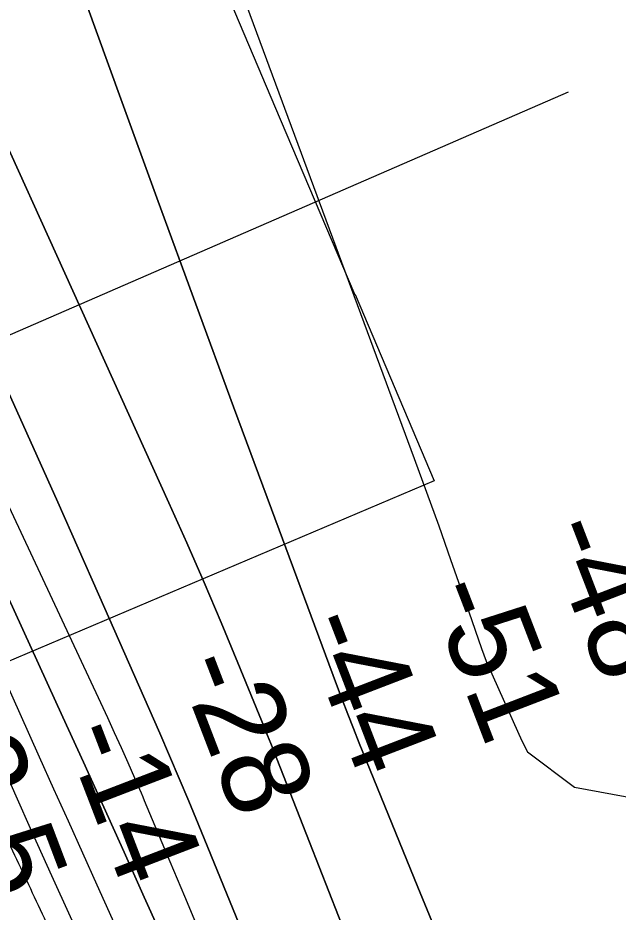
# Model space of a CAD drawing. Extents: x 3684037 to 3722149, y 433263 to 459021.
# Drawn here: x 3706787 to 3707248, y 445146 to 445833 of the extents above; entities that cross this region are included whole.
import ezdxf

# ---------------------------------------------------------------- set-up
doc = ezdxf.new("R2010")
doc.units = 0
for name, color, linetype in [('V-RIVR-EDGE', 7, 'Continuous'), ('V-RIVR-RANG', 7, 'Continuous'), ('V-RRAP-RVMT', 7, 'Continuous'), ('V-TOPO-DPTH', 7, 'Continuous'), ('V-TOPO-MAJR', 7, 'Continuous'), ('V-TOPO-MINR', 7, 'Continuous'), ('V-TOPO-WATR', 7, 'Continuous')]:
    doc.layers.add(name, color=color, linetype=linetype)

msp = doc.modelspace()

# ---------------------------------------------------------------- linework, layer by layer
at = {"layer": 'V-RIVR-EDGE'}
for points in [[(3707057.63, 450460), (3707081.52, 450431), (3707105.39, 450392.51), (3707125.2, 450359), (3707163.49, 450300.12), (3707183.76, 450270.23), (3707206.7, 450223.15), (3707227.4, 450181.5), (3707252.17, 450142.1), (3707265.67, 450117.2), (3707275.12, 450098.64), (3707318.38, 450037.94), (3707353.07, 449985.41), (3707385.06, 449939.66), (3707406.23, 449908.41), (3707430.1, 449871.27), (3707455.78, 449833.68), (3707495.45, 449785.2), (3707517.08, 449753.49), (3707534.2, 449727.23), (3707562.13, 449687.82), (3707582.83, 449647.07), (3707592.72, 449623.99), (3707603.99, 449607.68), (3707632.37, 449565.11), (3707692.27, 449470.46), (3707727.83, 449403.91), (3707751.67, 449355.47), (3707768.33, 449325.13), (3707817.4, 449240), (3707854.79, 449182.03), (3707880.91, 449141.73), (3707898.94, 449116.36), (3707960.23, 449034.82), (3707990.86, 448990.44), (3708021.04, 448942.43), (3708046.24, 448893.54), (3708087.2, 448819.73), (3708107.48, 448788.94), (3708130.45, 448754.06), (3708144.4, 448727.8), (3708155.18, 448700.19), (3708176.37, 448674.82), (3708204.31, 448634.06), (3708224.57, 448599.19), (3708242.58, 448567.5), (3708259.67, 448533.09), (3708300.54, 448421.76), (3708313.13, 448390.98), (3708333.36, 448345.26), (3708350.46, 448310.4), (3708400.43, 448222.56), (3708436, 448162.79), (3708462.58, 448121.12), (3708493.64, 448064.07), (3708520.62, 448004.32), (3708547.17, 447952.26), (3708560.65, 447921.03), (3708599.29, 447820.1), (3708618.62, 447774.38), (3708636.6, 447732.29), (3708686.04, 447611.44), (3708708.97, 447557.58), (3708728.76, 447517.74), (3708790.87, 447400.93), (3708813.79, 447342.99), (3708823.69, 447322.62), (3708832.7, 447310.39), (3708843.99, 447304.94), (3708854.83, 447299.94), (3708866.57, 447292.22), (3708878.28, 447274.56), (3708903.02, 447223.86), (3708928.62, 447154.16), (3708946.56, 447092.62), (3708972.63, 447032.42), (3709004.55, 446957.28), (3709022.09, 446919.26), (3709036.9, 446872.65), (3709065.65, 446798.42), (3709084.55, 446762.2), (3709116.06, 446705.15), (3709133.17, 446676.17), (3709190.81, 446579.27), (3709228.65, 446520.4), (3709242.18, 446506.8), (3709273.72, 446461.5), (3709296.22, 446418.04), (3709323.65, 446357.84), (3709346.13, 446307.14), (3709405.05, 446179.94), (3709417.62, 446143.28), (3709426.98, 446089), (3709431.45, 446069.09), (3709442.24, 446043.29), (3709459.81, 446017.93), (3709485.03, 445975.81), (3709516.54, 445917.41), (3709528.22, 445886.18), (3709547.07, 445830.07), (3709579.84, 445736.39), (3709592.41, 445699.28), (3709614.43, 445642.25), (3709638.73, 445596.07), (3709660.32, 445552.16), (3709689.1, 445487.43), (3709716.1, 445435.36), (3709727.8, 445413.18), (3709766.95, 445336.67), (3709796.19, 445272.84), (3709817.77, 445223.5), (3709885.21, 445070.05), (3709914.01, 445011.65), (3709955.32, 444895.8), (3709967.01, 444870), (3709990.89, 444833.77), (3710021.5, 444778.98), (3710062.05, 444721.45), (3710099, 444671.17), (3710125.54, 444614.59), (3710149.37, 444558.91), (3710206.48, 444434.88), (3710232.57, 444377.84), (3710255.95, 444325.79), (3710301.83, 444226.65), (3710336.44, 444144.73), (3710353.07, 444103.09), (3710397.08, 443983.15), (3710422.25, 443922.96), (3710475.81, 443823.35), (3710506.44, 443776.25), (3710521.29, 443745.01), (3710531.13, 443701.58), (3710571.1, 443591.61), (3710592.23, 443543.17), (3710610.23, 443506.96), (3710643.1, 443453.52), (3710685.41, 443374.74), (3710721.42, 443310.44), (3710726.82, 443298.22), (3710725.87, 443280.14), (3710724.91, 443258.89), (3710728.49, 443241.7), (3710736.59, 443228.11), (3710746.51, 443216.79), (3710761.87, 443209.97), (3710784.47, 443208.1), (3710799.86, 443212.58), (3710819.78, 443223.39), (3710828.83, 443224.27), (3710831.98, 443222), (3710845.47, 443189.86), (3710847.7, 443178.55), (3710844.52, 443169.52), (3710837.71, 443158.23), (3710824.1, 443142.44), (3710796, 443115.83), (3710790.11, 443110.87), (3710787.84, 443107.71), (3710786.47, 443099.58), (3710789.13, 443080.58), (3710800.82, 443053.87), (3710807.11, 443036.22), (3710810.72, 443032.6), (3710815.22, 443023.09), (3710815.19, 443014.5), (3710814.27, 443006.82), (3710817.86, 442996.41), (3710822.81, 442987.35), (3710832.3, 442981.9), (3710839.97, 442976.46), (3710855.3, 442958.33), (3710863.4, 442945.65), (3710869.69, 442927.55), (3710881.85, 442907.17)], [(3705459.26, 448025.43), (3705478.18, 447991.02), (3705490.65, 447962.68), (3705497.89, 447946.89), (3705515.2, 447915.31), (3705550.22, 447853.76), (3705577.2, 447806.38), (3705592.09, 447777.23), (3705613.01, 447735.52), (3705627.09, 447702.74), (3705648.41, 447660.63), (3705670.94, 447613.26), (3705688.64, 447575.61), (3705703.12, 447542.82), (3705728.05, 447487.77), (3705750.16, 447433.12), (3705764.23, 447399.52), (3705787.56, 447350.54), (3705800.43, 447321.8), (3705823.77, 447277.66), (3705853.13, 447212.89), (3705867.2, 447179.7), (3705884.51, 447148.52), (3705906.22, 447095.49), (3705936, 447039.61), (3705952.47, 446996.31), (3705954.47, 446986.6), (3705964.51, 446959.07), (3705978.19, 446928.31), (3706001.93, 446883.77), (3706017.22, 446850.17), (3706031.3, 446824.25), (3706060.3, 446774.85), (3706084.87, 446736.78), (3706095.75, 446723.41), (3706096.15, 446720.17), (3706091.28, 446714.52), (3706089.66, 446713.31), (3706090.46, 446708.86), (3706096.11, 446705.61), (3706102.98, 446703.57), (3706108.63, 446696.69), (3706116.28, 446683.32), (3706129.96, 446657.01), (3706163.36, 446591.82), (3706169.39, 446575.63), (3706187.09, 446537.58), (3706212.81, 446473.62), (3706230.09, 446432.33), (3706247.4, 446398.32), (3706265.12, 446371.19), (3706278.81, 446345.27), (3706293.68, 446309.65), (3706314.59, 446262.29), (3706333.51, 446225.85), (3706356.04, 446180.1), (3706380.19, 446133.54), (3706396.28, 446102.36), (3706412.79, 446074.82), (3706429.69, 446038.79), (3706446.98, 445997.91), (3706455.38, 445962.3), (3706478.24, 445886.22), (3706492.71, 445852.22), (3706510.4, 445809.72), (3706528.1, 445771.66), (3706558.26, 445705.27), (3706582.81, 445657.09), (3706597.69, 445624.3), (3706628.26, 445558.31), (3706659.61, 445483.02), (3706677.69, 445432.84), (3706696.97, 445381.03), (3706750.05, 445262.42), (3706782.63, 445193.19), (3706806.77, 445141.78), (3706827.68, 445093.6), (3706850.97, 445029.25), (3706864.2, 444984.33), (3706871.8, 444949.54), (3706889.46, 444896.93), (3706899.9, 444865.77), (3706912.35, 444832.17), (3706928.85, 444798.16), (3706942.54, 444773.46), (3706966.27, 444725.28), (3706990.42, 444679.53), (3707016.98, 444624.47), (3707033.86, 444586.01), (3707080.51, 444481.98), (3707095.38, 444444.74), (3707112.27, 444405.07), (3707123.13, 444381.18), (3707171.39, 444273.5), (3707203.15, 444200.64), (3707218.02, 444163.8), (3707250.2, 444096.19), (3707257.43, 444074.34), (3707269.88, 444041.55), (3707288.36, 443990.56), (3707304.03, 443950.08), (3707342.97, 443837.97), (3707365.86, 443772.01), (3707378.69, 443728.71), (3707379.87, 443714.15), (3707381.06, 443702.82), (3707387.47, 443682.18), (3707398.33, 443657.08), (3707418.05, 443619.03), (3707438.98, 443578.54), (3707454.25, 443542.11), (3707473.14, 443492.73), (3707483.18, 443464.39), (3707531.06, 443368.04), (3707542.73, 443344.96), (3707550.76, 443323.91), (3707556.78, 443302.46), (3707556.76, 443297.61), (3707558.76, 443289.12), (3707568.43, 443273.32), (3707583.72, 443244.57), (3707593.78, 443221.9), (3707598.21, 443213.4), (3707609.51, 443204.88), (3707611.91, 443195.17), (3707611.87, 443180.61), (3707615.48, 443168.07), (3707621.91, 443150.26), (3707634.38, 443126.78), (3707648.07, 443102.08), (3707655.3, 443081.84), (3707660.54, 443073.33), (3707674.23, 443051.47), (3707678.64, 443034.07), (3707682.63, 443015.46), (3707689.47, 442998.45), (3707701.92, 442964.46), (3707713.96, 442928.44), (3707721.18, 442903.35), (3707726.4, 442888.78), (3707738.08, 442871.77), (3707743.71, 442857.2), (3707744.49, 442845.06), (3707747.27, 442826.05), (3707753.71, 442815.52), (3707762.98, 442801.35), (3707770.21, 442783.94), (3707772.59, 442762.1), (3707776.17, 442738.23), (3707779.76, 442720.03), (3707786.59, 442702.62), (3707805.5, 442663.35), (3707822.8, 442627.32), (3707832.03, 442599.39), (3707839.25, 442573.9), (3707845.68, 442561.35), (3707852.54, 442552.44), (3707860.19, 442541.9), (3707869.47, 442530.56), (3707886.39, 442507.87), (3707898.86, 442479.94), (3707916.14, 442434.61), (3707928.58, 442395.76), (3707943.44, 442356.5), (3707965.58, 442316.41), (3707989.73, 442269.04), (3708009.84, 442227.74), (3708024.72, 442192.53), (3708061.32, 442114.39), (3708074.2, 442088.48), (3708094.31, 442045.57), (3708116.02, 441996.58), (3708126.06, 441968.25), (3708137.69, 441927.79), (3708147.33, 441899.46), (3708157.76, 441868.3), (3708179.06, 441812.44), (3708203.96, 441746.87), (3708227.69, 441693.84), (3708249.81, 441646.07), (3708265.1, 441615.3), (3708271.52, 441595.87), (3708278.37, 441582.11), (3708308.11, 441508.44), (3708330.63, 441457.84), (3708349.91, 441405.22), (3708369.56, 441340.07), (3708384.01, 441295.55), (3708395.26, 441268.43), (3708411.76, 441234.83), (3708423.42, 441209.33), (3708441.12, 441169.65), (3708458.42, 441135.24), (3708469.27, 441110.55), (3708475.29, 441089.1), (3708486.95, 441061.57), (3708507.06, 441017.45), (3708523.54, 440978.59), (3708539.2, 440935.69), (3708564.14, 440883.06), (3708587.09, 440841.35), (3708595.14, 440826.77), (3708600.35, 440809.37), (3708606.75, 440778.22), (3708615.59, 440755.15), (3708636.86, 440692.01), (3708652.92, 440644.26), (3708673.41, 440592.04), (3708688.69, 440554.4), (3708705.96, 440506.64), (3708725.66, 440462.92), (3708743.35, 440422.44), (3708759.44, 440387.62), (3708800.05, 440293.31), (3708820.96, 440246.35), (3708835.03, 440211.54), (3708849.1, 440180.36), (3708876.06, 440124.9), (3708892.16, 440093.72), (3708912.28, 440054.85), (3708922.33, 440030.97), (3708931.96, 439999.81), (3708939.18, 439978.77), (3708948.02, 439954.08), (3708952.41, 439931.83), (3708956, 439911.6), (3708960.02, 439899.46), (3708969.65, 439870.32), (3708986.94, 439829.84), (3708999.38, 439794.22), (3709014.65, 439755.37), (3709034.75, 439705.18), (3709046.8, 439671.58), (3709063.28, 439633.13), (3709075.77, 439614.5), (3709093.1, 439592.62), (3709106, 439574.39), (3709121.71, 439548.87), (3709151.47, 439484.1), (3709171.6, 439447.25), (3709197.38, 439407.56), (3709211.05, 439376.8), (3709222.31, 439350.08), (3709240.4, 439308.79), (3709252.87, 439281.67), (3709266.15, 439254.94), (3709270.98, 439245.63), (3709296.34, 439199.88), (3709313.22, 439158.99), (3709331.31, 439114.87), (3709341.34, 439082.5), (3709360.25, 439046.46), (3709378.76, 439008.81), (3709407.72, 438944.44), (3709416.41, 438923.63)]]:
    msp.add_spline(points, degree=3, dxfattribs=at)
at = {"layer": 'V-RIVR-RANG'}
msp.add_line((3706512.43, 445472.91), (3707209.38, 445776.01), dxfattribs=at)
at = {"layer": 'V-RRAP-RVMT'}
msp.add_lwpolyline([(3706935.81, 445878.4), (3706988.11, 445755.12), (3706988.19, 445755.16), (3707045.41, 445620.25), (3707045.73, 445620.38), (3707106.36, 445477.45), (3706725.99, 445316.09), (3706668.76, 445450.99), (3706667.47, 445450.46), (3706611.03, 445583.49), (3706609.73, 445582.95), (3706553.23, 445716.1), (3706552.39, 445715.74), (3706491.72, 445858.71)], dxfattribs=at)
at = {"layer": 'V-TOPO-DPTH'}
for points in [[(3707276.95, 444736.81), (3707205.42, 444900.75), (3707176.96, 444966.65), (3707148.83, 445032.68), (3707121.2, 445098.93), (3707093.89, 445165.31), (3707048.85, 445275.94), (3707044.36, 445287.13), (3707039.94, 445298.34), (3707035.62, 445309.6), (3707031.37, 445320.89), (3706981.4, 445455.61), (3706952.3, 445534.31), (3706923.32, 445613.05), (3706894.49, 445691.85), (3706865.78, 445770.7), (3706795, 445965.69)], [(3706795, 445965.69), (3706865.78, 445770.7), (3706894.49, 445691.85), (3706923.32, 445613.05), (3706952.3, 445534.31), (3706981.4, 445455.61), (3707031.37, 445320.89), (3707035.62, 445309.6), (3707039.94, 445298.34), (3707044.36, 445287.13), (3707048.85, 445275.94), (3707093.89, 445165.31), (3707121.2, 445098.93), (3707148.83, 445032.68), (3707176.96, 444966.65), (3707205.42, 444900.75), (3707276.95, 444736.81)], [(3707296.08, 444476.12), (3707239.39, 444617.55), (3707232.05, 444635.93), (3707224.73, 444654.33), (3707217.45, 444672.73), (3707210.2, 444691.15), (3707070.1, 445048.22), (3707055.22, 445086.15), (3707040.35, 445124.07), (3707025.49, 445162), (3707010.63, 445199.93), (3706985.62, 445263.8), (3706983.26, 445269.79), (3706980.88, 445275.78), (3706978.47, 445281.76), (3706976.04, 445287.73), (3706955.59, 445337.66), (3706942.76, 445368.52), (3706929.7, 445399.29), (3706916.31, 445429.9), (3706902.69, 445460.42), (3706688.76, 445932.79)], [(3706688.76, 445932.79), (3706902.69, 445460.42), (3706916.31, 445429.9), (3706929.7, 445399.29), (3706942.76, 445368.52), (3706955.59, 445337.66), (3706976.04, 445287.73), (3706978.47, 445281.76), (3706980.88, 445275.78), (3706983.26, 445269.79), (3706985.62, 445263.8), (3707010.63, 445199.93), (3707025.49, 445162), (3707040.35, 445124.07), (3707055.22, 445086.15), (3707070.1, 445048.22), (3707210.2, 444691.15), (3707217.45, 444672.73), (3707224.73, 444654.33), (3707232.05, 444635.93), (3707239.39, 444617.55), (3707296.08, 444476.12)], [(3706559.65, 445871.06), (3706587.08, 445809.81), (3706605.7, 445768.36), (3706624.38, 445726.95), (3706643.16, 445685.58), (3706662.01, 445644.24), (3706821.33, 445295.8), (3706837.05, 445261.32), (3706852.7, 445226.8), (3706868.26, 445192.25), (3706883.77, 445157.67), (3706894.87, 445132.82), (3706915.73, 445085.74), (3706936.4, 445038.57), (3706956.79, 444991.27), (3706976.98, 444943.89), (3707099.23, 444654.57), (3707107.92, 444633.87), (3707116.56, 444613.15), (3707125.1, 444592.39), (3707133.59, 444571.61), (3707239.95, 444309.69)], [(3707239.95, 444309.69), (3707133.59, 444571.61), (3707125.1, 444592.39), (3707116.56, 444613.15), (3707107.92, 444633.87), (3707099.23, 444654.57), (3706976.98, 444943.89), (3706956.79, 444991.27), (3706936.4, 445038.57), (3706915.73, 445085.74), (3706894.87, 445132.82), (3706883.77, 445157.67), (3706868.26, 445192.25), (3706852.7, 445226.8), (3706837.05, 445261.32), (3706821.33, 445295.8), (3706662.01, 445644.24), (3706643.16, 445685.58), (3706624.38, 445726.95), (3706605.7, 445768.36), (3706587.08, 445809.81), (3706559.65, 445871.06)], [(3707117.33, 444743.49), (3706925.06, 445214.01), (3706917.84, 445231.48), (3706910.54, 445248.9), (3706903.1, 445266.27), (3706895.57, 445283.6), (3706848.62, 445390.48), (3706817.33, 445461.13), (3706785.76, 445531.64), (3706753.75, 445601.96), (3706721.45, 445672.15), (3706633.07, 445862.68)], [(3706633.07, 445862.68), (3706721.45, 445672.15), (3706753.75, 445601.96), (3706785.76, 445531.64), (3706817.33, 445461.13), (3706848.62, 445390.48), (3706895.57, 445283.6), (3706903.1, 445266.27), (3706910.54, 445248.9), (3706917.84, 445231.48), (3706925.06, 445214.01), (3707117.33, 444743.49)], [(3706521.35, 445845.84), (3706714.67, 445396.9), (3706728.44, 445365.02), (3706742.26, 445333.16), (3706756.16, 445301.33), (3706770.1, 445269.52), (3706784.14, 445237.76), (3706798.26, 445206.03), (3706812.5, 445174.35), (3706826.81, 445142.71), (3707074.74, 444597.24), (3707390.51, 443786.32)]]:
    msp.add_lwpolyline(points, dxfattribs=at)
at = {"layer": 'V-TOPO-MAJR'}
msp.add_lwpolyline([(3706904.64, 445998.26), (3707090.97, 445494.59), (3707100.44, 445468.74), (3707109.8, 445442.85), (3707118.99, 445416.91), (3707128.08, 445390.92), (3707142.73, 445348.62), (3707144.47, 445343.79), (3707146.31, 445338.98), (3707148.27, 445334.23), (3707173.6, 445277.66), (3707177.94, 445269.3), (3707213.97, 445242.26), (3707272.45, 445231.48)], dxfattribs=at)
at = {"layer": 'V-TOPO-MINR'}
for points in [[(3706795, 445965.69), (3706865.78, 445770.7), (3706894.49, 445691.85), (3706923.32, 445613.05), (3706952.3, 445534.31), (3706981.4, 445455.61), (3707031.37, 445320.89), (3707035.62, 445309.6), (3707039.94, 445298.34), (3707044.36, 445287.13), (3707048.85, 445275.94), (3707093.89, 445165.31), (3707121.2, 445098.93), (3707148.83, 445032.68), (3707176.96, 444966.65), (3707205.42, 444900.75), (3707276.95, 444736.81)], [(3706688.76, 445932.79), (3706902.69, 445460.42), (3706916.31, 445429.9), (3706929.7, 445399.29), (3706942.76, 445368.52), (3706955.59, 445337.66), (3706976.04, 445287.73), (3706978.47, 445281.76), (3706980.88, 445275.78), (3706983.26, 445269.79), (3706985.62, 445263.8), (3707010.63, 445199.93), (3707025.49, 445162), (3707040.35, 445124.07), (3707055.22, 445086.15), (3707070.1, 445048.22), (3707210.2, 444691.15), (3707217.45, 444672.73), (3707224.73, 444654.33), (3707232.05, 444635.93), (3707239.39, 444617.55), (3707296.08, 444476.12)], [(3706571.69, 445902.3), (3706850.05, 445307.29), (3706855.4, 445295.77), (3706860.7, 445284.21), (3706865.92, 445272.63), (3706871.08, 445261.01), (3706878.8, 445243.52), (3706880.06, 445240.64), (3706881.32, 445237.75), (3706882.55, 445234.85), (3706883.78, 445231.95), (3706903.49, 445184.98), (3706914.57, 445158.58), (3706925.64, 445132.19), (3706936.71, 445105.8), (3706947.77, 445079.41), (3707112.75, 444685.88), (3707126.11, 444653.87), (3707139.42, 444621.85), (3707152.63, 444589.79), (3707165.79, 444557.7)], [(3706559.65, 445871.06), (3706587.08, 445809.81), (3706605.7, 445768.36), (3706624.38, 445726.95), (3706643.16, 445685.58), (3706662.01, 445644.24), (3706821.33, 445295.8), (3706837.05, 445261.32), (3706852.7, 445226.8), (3706868.26, 445192.25), (3706883.77, 445157.67), (3706894.87, 445132.82), (3706915.73, 445085.74), (3706936.4, 445038.57), (3706956.79, 444991.27), (3706976.98, 444943.89), (3707099.23, 444654.57), (3707107.92, 444633.87), (3707116.56, 444613.15), (3707125.1, 444592.39), (3707133.59, 444571.61), (3707239.95, 444309.69)], [(3706633.07, 445862.68), (3706721.45, 445672.15), (3706753.75, 445601.96), (3706785.76, 445531.64), (3706817.33, 445461.13), (3706848.62, 445390.48), (3706895.57, 445283.6), (3706903.1, 445266.27), (3706910.54, 445248.9), (3706917.84, 445231.48), (3706925.06, 445214.01), (3707117.33, 444743.49)], [(3706550.18, 445834.82), (3706609.55, 445699.95), (3706645.19, 445619.21), (3706680.95, 445538.52), (3706716.88, 445457.91), (3706752.92, 445377.35), (3706803.14, 445265.41), (3706814.16, 445240.86), (3706825.2, 445216.31), (3706836.24, 445191.76), (3706847.3, 445167.22), (3706962.45, 444911.8), (3706985.17, 444860.93), (3707007.66, 444809.96), (3707029.79, 444758.84), (3707051.69, 444707.61), (3707086.63, 444625.1), (3707090.85, 444615.04), (3707095.05, 444604.97), (3707099.19, 444594.87), (3707103.29, 444584.76), (3707348.36, 443976.64)]]:
    msp.add_lwpolyline(points, dxfattribs=at)
at = {"layer": 'V-TOPO-WATR'}
msp.add_lwpolyline([(3706521.35, 445845.84), (3706714.67, 445396.9), (3706728.44, 445365.02), (3706742.26, 445333.16), (3706756.16, 445301.33), (3706770.1, 445269.52), (3706784.14, 445237.76), (3706798.26, 445206.03), (3706812.5, 445174.35), (3706826.81, 445142.71), (3707074.74, 444597.24), (3707390.51, 443786.32)], dxfattribs=at)

# ---------------------------------------------------------------- texts
at = {"layer": 'V-RIVR-RANG'}
for s, rotation, p in [('-48', 291.04983, (3707189.53, 445439.83)), ('-51', 291.04983, (3707100.57, 445392.58)), ('-44', 291.04983, (3707002.98, 445367.72)), ('-28', 291.04983, (3706908.15, 445335.73)), ('-14', 291.04983, (3706821.08, 445283.54)), ('3.5', 290.76833, (3706720.42, 445267.86))]:
    msp.add_text(s, height=67, rotation=rotation, dxfattribs=at).set_placement(p)

doc.saveas('drawing.dxf')
